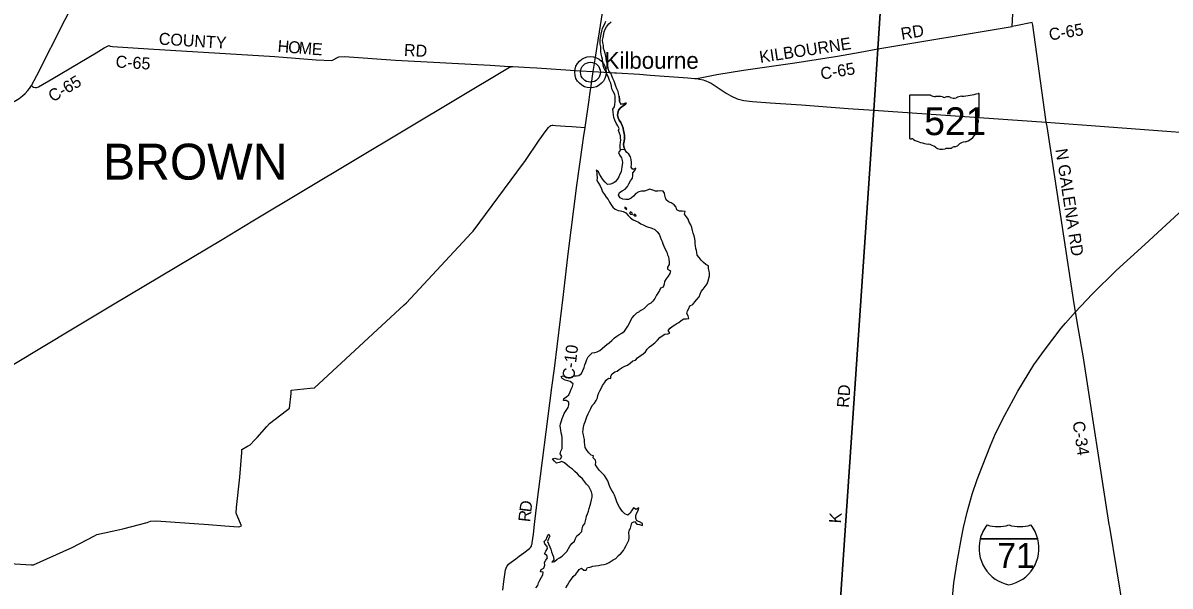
# Model space of a CAD drawing. Extents: x 1674899 to 2057726, y 653888 to 988278.
# Drawn here: x 1826739 to 1855438, y 836141 to 850231 of the extents above; entities that cross this region are included whole.
import ezdxf

# ---------------------------------------------------------------- set-up
doc = ezdxf.new("R2010")
doc.units = 0
for name, color, linetype in [('GM_X_County_Road', 7, 'Continuous'), ('GM_X_County_Road_Text', 7, 'Continuous'), ('GM_X_Interstate_Location', 7, 'Continuous'), ('GM_X_Interstate_Route', 7, 'Continuous'), ('GM_X_Interstate_Shield', 7, 'Continuous'), ('GM_X_Major_Lake', 7, 'Continuous'), ('GM_X_Major_River', 7, 'Continuous'), ('GM_X_State_Location', 7, 'Continuous'), ('GM_X_State_Route', 7, 'Continuous'), ('GM_X_State_Shield', 7, 'Continuous'), ('GM_X_Township', 7, 'Continuous'), ('GM_X_Township_Text', 7, 'Continuous'), ('GM_X_Unincorporated', 7, 'Continuous'), ('GM_X_Unincorporated_Location', 7, 'Continuous'), ('GM_X_Unincorporated_Text', 7, 'Continuous'), ('GM_X_US_Route', 7, 'Continuous'), ('SH_Data', 7, 'Continuous')]:
    doc.layers.add(name, color=color, linetype=linetype)

msp = doc.modelspace()

# ---------------------------------------------------------------- linework, layer by layer
at = {"layer": 'GM_X_County_Road'}
for points in [[(1841006, 849018), (1841051, 849314), (1841101, 849645), (1841295, 850857)], [(1852342, 847746), (1852332, 847819), (1852002, 850172), (1851992, 850242), (1851578, 850159), (1851485, 850140), (1851503, 850457)], [(1848128, 849585), (1851485, 850140)], [(1827483, 848845), (1828569, 849486), (1828773, 849606), (1828890, 849668)], [(1828890, 849668), (1828890, 849668), (1828924, 849648), (1828977, 849643), (1829879, 849585), (1833037, 849389), (1834076, 849311), (1834469, 849288), (1834642, 849380), (1834781, 849392), (1836063, 849299), (1838431, 849174), (1838783, 849153), (1838998, 849141)], [(1843595, 848838), (1843637, 848852), (1843852, 848894), (1844102, 848937), (1844768, 849049), (1846050, 849232), (1847118, 849400), (1847685, 849497), (1848128, 849585)], [(1846971, 832575), (1846971, 832575), (1847065, 833986), (1848030, 848046), (1848128, 849585)], [(1838743, 836040), (1838773, 836253), (1838796, 836429), (1838814, 836551), (1838826, 836590), (1838844, 836629), (1838867, 836664), (1838885, 836685), (1838954, 836740), (1839072, 836824), (1839157, 836890), (1839273, 836974), (1839413, 837081), (1839426, 837095), (1839438, 837110), (1839458, 837143), (1839466, 837161), (1839472, 837179), (1839477, 837198), (1839478, 837221), (1839510, 837440), (1839538, 837684), (1839547, 837760), (1839596, 838176), (1839967, 841111), (1840035, 841581), (1840259, 843439), (1840381, 844450), (1840596, 846166), (1840736, 847171), (1840762, 847354), (1840807, 847615), (1840906, 848311), (1840922, 848444), (1840955, 848656), (1841006, 849018)], [(1826954, 848664), (1826976, 848639), (1827002, 848628), (1827054, 848615), (1827084, 848617), (1827126, 848635), (1827483, 848845)], [(1824939, 836797), (1826941, 836673), (1827000, 836670), (1827915, 837079), (1827969, 837103), (1828528, 837401), (1828591, 837434), (1829159, 837555), (1829234, 837570), (1829847, 837731), (1829932, 837765), (1830068, 837770), (1831380, 837679), (1831789, 837651), (1832132, 837627), (1832164, 837633), (1832207, 837647), (1832086, 837925), (1832077, 837968), (1832081, 838107), (1832167, 838864), (1832211, 839479), (1832217, 839559), (1832354, 839640), (1832420, 839679), (1832530, 839793), (1832596, 839862), (1832843, 840137), (1832910, 840211), (1833329, 840531), (1833411, 840594), (1833446, 840962), (1833453, 841041), (1833926, 841092), (1834029, 841103), (1836280, 843180), (1836334, 843229), (1837952, 844970), (1838003, 845024), (1839263, 846719), (1839296, 846763), (1839657, 847296), (1839829, 847544), (1839890, 847618), (1839921, 847646), (1839949, 847661), (1839978, 847670), (1839994, 847672), (1840065, 847668), (1840312, 847648), (1840471, 847640), (1840580, 847631), (1840807, 847615)], [(1854821, 832136), (1854806, 832276), (1853927, 837618), (1853916, 837681), (1853270, 841855), (1853135, 842607), (1853071, 843001), (1853019, 843312), (1852359, 847640), (1852342, 847746)]]:
    msp.add_lwpolyline(points, dxfattribs=at)
at = {"layer": 'GM_X_Interstate_Route'}
for points in [[(1853497, 843457), (1854091, 844035), (1854810, 844689), (1856408, 846161), (1857196, 846884), (1857351, 847028)], [(1852825, 842723), (1853071, 843001), (1853486, 843445), (1853497, 843457)], [(1849960, 835440), (1849991, 835852), (1850027, 836225), (1850112, 836751), (1850219, 837345), (1850270, 837606), (1850358, 837993), (1850490, 838443), (1850609, 838810), (1850743, 839153), (1850946, 839662), (1851071, 839958), (1851303, 840416), (1851627, 841020), (1852032, 841680), (1852294, 842043), (1852715, 842598), (1852825, 842723)]]:
    msp.add_lwpolyline(points, dxfattribs=at)
at = {"layer": 'GM_X_Interstate_Shield'}
for p, q in [((1850686, 837319), (1852129, 837319)), ((1852129, 837319), (1850686, 837319)), ((1852129, 837319), (1850686, 837319))]:
    msp.add_line(p, q, dxfattribs=at)
for centre, start, end in [((1851595, 837089), 141.669, 165.8066), ((1851133, 838567), 253.0091, 286.9909), ((1851681, 838567), 253.0091, 286.9909), ((1851220, 837089), 14.1934, 38.331), ((1851595, 837089), 165.8066, 258.463), ((1851220, 837089), 281.537, 14.1934)]:
    msp.add_arc(centre, 938, start, end, dxfattribs=at)
at = {"layer": 'GM_X_Major_Lake'}
msp.add_line((1841794, 847067), (1841688, 847052), dxfattribs=at)
for points in [[(1841688, 847052), (1841636, 846990), (1841670, 846918), (1841715, 846857), (1841731, 846793), (1841737, 846743), (1841731, 846679), (1841720, 846623), (1841712, 846573), (1841702, 846509), (1841674, 846449), (1841648, 846383), (1841607, 846315), (1841553, 846256), (1841503, 846220), (1841435, 846194), (1841361, 846192), (1841301, 846244), (1841250, 846315), (1841202, 846381), (1841166, 846447), (1841135, 846507), (1841079, 846545), (1841096, 846477), (1841100, 846427), (1841102, 846359), (1841100, 846287), (1841140, 846223), (1841181, 846157), (1841217, 846081), (1841239, 846008), (1841290, 845940), (1841326, 845874), (1841380, 845812), (1841412, 845744), (1841451, 845677), (1841499, 845625), (1841559, 845571), (1841627, 845541), (1841687, 845529), (1841753, 845510), (1841818, 845478), (1841880, 845414), (1841942, 845353), (1842002, 845301), (1842067, 845277), (1842135, 845243), (1842201, 845204), (1842273, 845170), (1842339, 845140), (1842474, 845099), (1842544, 845061), (1842604, 845007), (1842652, 844945), (1842682, 844880), (1842707, 844816), (1842729, 844762), (1842751, 844704), (1842771, 844644), (1842808, 844574), (1842844, 844496), (1842868, 844429), (1842886, 844377), (1842897, 844311), (1842903, 844251), (1842907, 844185), (1842867, 844117), (1842865, 844067), (1842938, 844027), (1842924, 843959), (1842880, 843897), (1842830, 843827), (1842790, 843763), (1842777, 843697), (1842759, 843623), (1842693, 843597), (1842661, 843537), (1842623, 843473), (1842593, 843416), (1842548, 843340), (1842500, 843266), (1842446, 843220), (1842384, 843190), (1842330, 843136), (1842276, 843076), (1842212, 843047), (1842162, 843019), (1842162, 843013)], [(1843917, 843901), (1843913, 843907), (1843913, 843971), (1843904, 844021), (1843890, 844085), (1843892, 844154), (1843824, 844186), (1843766, 844238), (1843705, 844298), (1843655, 844359), (1843609, 844423), (1843599, 844489), (1843592, 844539), (1843576, 844589), (1843564, 844653), (1843558, 844707), (1843556, 844771), (1843551, 844831), (1843533, 844903), (1843509, 844972), (1843487, 845040), (1843476, 845114), (1843448, 845178), (1843406, 845248), (1843382, 845318), (1843339, 845381), (1843293, 845445), (1843303, 845513), (1843233, 845521), (1843165, 845523), (1843100, 845556), (1843080, 845622), (1843028, 845682), (1842960, 845726), (1842892, 845752), (1842829, 845803), (1842815, 845853), (1842799, 845921), (1842791, 845971), (1842757, 846025), (1842690, 846027), (1842626, 846024), (1842562, 846026), (1842498, 846048), (1842426, 846068), (1842356, 846047), (1842290, 846021), (1842216, 846019), (1842144, 846009), (1842076, 845963), (1842014, 845900), (1841952, 845850), (1841885, 845812), (1841818, 845812), (1841750, 845819), (1841682, 845851), (1841640, 845923), (1841666, 845989), (1841732, 846033), (1841802, 846071), (1841865, 846136), (1841893, 846208), (1841935, 846278), (1841989, 846348), (1841993, 846412), (1841998, 846480), (1842044, 846542), (1842074, 846594), (1842000, 846564), (1841958, 846620), (1841960, 846688), (1841961, 846739), (1841957, 846813), (1841939, 846881), (1841897, 846945), (1841836, 847001), (1841794, 847067)], [(1843917, 843901), (1843913, 843907), (1843913, 843971), (1843904, 844021), (1843890, 844085), (1843892, 844154), (1843824, 844186), (1843766, 844238), (1843705, 844298), (1843655, 844359), (1843609, 844423), (1843599, 844489), (1843592, 844539), (1843576, 844589), (1843564, 844653), (1843558, 844707), (1843556, 844771), (1843551, 844831), (1843533, 844903), (1843509, 844972), (1843487, 845040), (1843476, 845114), (1843448, 845178), (1843406, 845248), (1843382, 845318), (1843339, 845381), (1843293, 845445), (1843303, 845513), (1843233, 845521), (1843165, 845523), (1843100, 845556), (1843080, 845622), (1843028, 845682), (1842960, 845726), (1842892, 845752), (1842829, 845803), (1842815, 845853), (1842799, 845921), (1842791, 845971), (1842757, 846025), (1842690, 846027), (1842626, 846024), (1842562, 846026), (1842498, 846048), (1842426, 846068), (1842356, 846047), (1842290, 846021), (1842216, 846019), (1842144, 846009), (1842076, 845963), (1842014, 845900), (1841952, 845850), (1841885, 845812), (1841818, 845812), (1841750, 845819), (1841682, 845851), (1841640, 845923), (1841666, 845989), (1841732, 846033), (1841802, 846071), (1841865, 846136), (1841893, 846208), (1841935, 846278), (1841989, 846348), (1841993, 846412), (1841998, 846480), (1842044, 846542), (1842074, 846594), (1842000, 846564), (1841958, 846620), (1841960, 846688), (1841961, 846739), (1841957, 846813), (1841939, 846881), (1841897, 846945), (1841836, 847001), (1841794, 847067)], [(1841799, 845622), (1841793, 845596), (1841843, 845565)], [(1841843, 845565), (1841833, 845609), (1841799, 845622)], [(1841991, 845437), (1841982, 845472), (1841938, 845504), (1841910, 845472)], [(1841910, 845472), (1841941, 845448), (1841991, 845437)], [(1842071, 845423), (1842047, 845447), (1842013, 845431)], [(1842013, 845431), (1842041, 845403), (1842081, 845395), (1842071, 845423)], [(1843547, 843252), (1843601, 843310), (1843656, 843380), (1843682, 843446), (1843710, 843508), (1843756, 843572), (1843810, 843635), (1843855, 843707), (1843881, 843777), (1843917, 843901)], [(1842011, 838095), (1841961, 838027), (1841927, 837961), (1841869, 837914), (1841801, 837948), (1841741, 838004), (1841699, 838068), (1841661, 838119), (1841618, 838187), (1841598, 838251), (1841584, 838301), (1841566, 838351), (1841541, 838417), (1841505, 838483), (1841463, 838546), (1841431, 838606), (1841403, 838674), (1841372, 838774), (1841334, 838842), (1841288, 838907), (1841227, 838965), (1841167, 839031), (1841113, 839103), (1841067, 839174), (1841072, 839238), (1841060, 839292), (1841008, 839346), (1841012, 839398), (1840952, 839420), (1840897, 839478), (1840843, 839545), (1840805, 839611), (1840797, 839677), (1840786, 839741), (1840784, 839805), (1840772, 839873), (1840762, 839923), (1840750, 839989), (1840755, 840059), (1840765, 840121), (1840783, 840193), (1840803, 840247), (1840830, 840325), (1840850, 840377), (1840876, 840447), (1840946, 840587), (1840981, 840659), (1841039, 840719), (1841081, 840787), (1841109, 840853), (1841125, 840907), (1841149, 840973), (1841172, 841027), (1841210, 841099), (1841242, 841163), (1841286, 841226), (1841326, 841294), (1841385, 841346), (1841450, 841336), (1841443, 841392), (1841479, 841454), (1841549, 841498), (1841603, 841522), (1841657, 841563), (1841727, 841607), (1841799, 841641), (1841861, 841667), (1841927, 841719), (1841994, 841780), (1842060, 841792), (1842112, 841854), (1842178, 841904), (1842246, 841942), (1842310, 842001), (1842352, 842067), (1842412, 842123), (1842474, 842167), (1842545, 842223), (1842613, 842293), (1842669, 842360), (1842727, 842406), (1842801, 842446), (1842871, 842456), (1842923, 842470), (1842885, 842532), (1842932, 842598), (1842984, 842638), (1843044, 842679), (1843096, 842709), (1843146, 842737), (1843210, 842783), (1843270, 842831), (1843336, 842830), (1843402, 842832), (1843384, 842900), (1843352, 842958), (1843363, 843024), (1843395, 843084), (1843427, 843150), (1843495, 843184), (1843547, 843252)], [(1840224, 839259), (1840156, 839235), (1840090, 839215), (1840039, 839267), (1839985, 839322), (1840049, 839341), (1840117, 839319), (1840189, 839321), (1840217, 839383), (1840181, 839449), (1840197, 839515), (1840227, 839581), (1840226, 839645), (1840230, 839725), (1840232, 839791), (1840230, 839861), (1840223, 839913), (1840207, 839977), (1840197, 840043), (1840189, 840093), (1840183, 840150), (1840184, 840204), (1840210, 840272), (1840232, 840333), (1840254, 840391), (1840282, 840463), (1840331, 840533), (1840377, 840611), (1840399, 840675), (1840393, 840743), (1840333, 840781), (1840266, 840780), (1840274, 840838), (1840334, 840876), (1840396, 840929), (1840428, 840999), (1840456, 841065), (1840489, 841131), (1840501, 841205), (1840433, 841256), (1840371, 841276), (1840303, 841290), (1840231, 841332), (1840206, 841382), (1840258, 841400), (1840333, 841360), (1840397, 841354), (1840451, 841368), (1840521, 841399), (1840585, 841405), (1840649, 841409), (1840711, 841463), (1840750, 841531), (1840778, 841607), (1840800, 841673), (1840820, 841737), (1840845, 841808), (1840877, 841874), (1840981, 841974), (1841043, 841986), (1841107, 842004), (1841169, 842034), (1841233, 842087), (1841295, 842147), (1841345, 842185), (1841406, 842229), (1841470, 842289), (1841542, 842356), (1841594, 842396), (1841646, 842428), (1841722, 842472), (1841786, 842518), (1841838, 842594), (1841873, 842648), (1841913, 842723), (1841943, 842791), (1841977, 842853), (1842029, 842913), (1842100, 842975), (1842162, 843013)], [(1839568, 836094), (1839620, 836158), (1839641, 836218), (1839667, 836290), (1839713, 836360), (1839743, 836422), (1839755, 836490), (1839688, 836500), (1839702, 836556), (1839768, 836588), (1839792, 836660), (1839786, 836728), (1839822, 836792), (1839863, 836844), (1839849, 836910), (1839787, 836946), (1839823, 837018), (1839859, 837084), (1839850, 837134), (1839792, 837196), (1839780, 837257), (1839828, 837310), (1839850, 837376), (1839897, 837440), (1839918, 837388), (1839886, 837322), (1839866, 837258), (1839890, 837196), (1839919, 837124), (1839943, 837062), (1839965, 836996), (1839991, 836932), (1840016, 836869), (1840020, 836797), (1839970, 836735), (1840036, 836753), (1840100, 836811), (1840166, 836847), (1840232, 836891), (1840289, 836944), (1840347, 837008), (1840425, 837138), (1840471, 837202), (1840535, 837266), (1840564, 837330), (1840594, 837396), (1840662, 837446), (1840724, 837507), (1840732, 837573), (1840749, 837639), (1840795, 837705), (1840815, 837771), (1840829, 837839), (1840837, 837889), (1840865, 837949), (1840888, 838019), (1840906, 838085), (1840932, 838163), (1840944, 838221), (1840965, 838295), (1840977, 838367), (1840979, 838435), (1840967, 838499), (1840931, 838564), (1840894, 838632), (1840842, 838694), (1840788, 838758), (1840739, 838824), (1840675, 838883), (1840609, 838949), (1840547, 839009), (1840484, 839068), (1840416, 839120), (1840352, 839170), (1840286, 839226), (1840224, 839259)], [(1840324, 836096), (1840362, 836166), (1840408, 836241), (1840452, 836307), (1840508, 836379), (1840569, 836439), (1840617, 836505), (1840655, 836557), (1840713, 836587), (1840773, 836536), (1840827, 836540), (1840863, 836606), (1840931, 836618), (1840999, 836638), (1841067, 836647), (1841137, 836657), (1841205, 836671), (1841269, 836681), (1841335, 836697), (1841401, 836730), (1841453, 836764), (1841503, 836796), (1841571, 836834), (1841639, 836902), (1841705, 836965), (1841762, 837031), (1841790, 837083), (1841828, 837155), (1841894, 837287), (1841903, 837351), (1841903, 837401), (1841901, 837463), (1841909, 837529), (1841935, 837589), (1841956, 837657), (1841974, 837727), (1842042, 837753), (1842098, 837687), (1842168, 837684), (1842235, 837658), (1842236, 837708), (1842168, 837750), (1842100, 837771), (1842074, 837841), (1842072, 837907), (1842099, 837975), (1842141, 838045), (1842147, 838099), (1842079, 838061), (1842011, 838095)]]:
    msp.add_lwpolyline(points, dxfattribs=at)
at = {"layer": 'GM_X_Major_River'}
msp.add_line((1841794, 847067), (1841688, 847052), dxfattribs=at)
for points in [[(1841521, 847865), (1841513, 847931), (1841505, 847999), (1841494, 848071), (1841538, 848135), (1841544, 848191), (1841552, 848259), (1841559, 848329), (1841559, 848393), (1841547, 848443), (1841507, 848514), (1841474, 848580), (1841462, 848650), (1841444, 848724), (1841412, 848794), (1841387, 848862), (1841331, 848991), (1841293, 849059), (1841268, 849109), (1841252, 849179), (1841244, 849245), (1841238, 849323), (1841219, 849387), (1841207, 849449), (1841197, 849513), (1841193, 849580), (1841194, 849636), (1841180, 849700), (1841176, 849752), (1841176, 849816), (1841194, 849898), (1841203, 849954), (1841223, 850022), (1841239, 850090), (1841267, 850154), (1841293, 850206), (1841320, 850272)], [(1841655, 848397), (1841639, 848463), (1841627, 848513), (1841597, 848581), (1841574, 848653), (1841550, 848726), (1841526, 848776), (1841496, 848844), (1841471, 848908), (1841447, 848978), (1841395, 849036), (1841383, 849100), (1841370, 849169), (1841358, 849221), (1841340, 849273), (1841326, 849351), (1841319, 849401), (1841305, 849465), (1841291, 849521), (1841267, 849593), (1841260, 849667), (1841250, 849733), (1841242, 849802), (1841258, 849870), (1841279, 850010), (1841307, 850076), (1841341, 850135), (1841399, 850211), (1841452, 850263)], [(1841655, 848397), (1841660, 848319), (1841664, 848265), (1841700, 848199), (1841768, 848204), (1841834, 848234), (1841807, 848190), (1841756, 848156), (1841686, 848107), (1841636, 848047), (1841625, 847977), (1841617, 847927), (1841627, 847861), (1841659, 847800), (1841696, 847736), (1841728, 847668), (1841756, 847602), (1841764, 847534), (1841779, 847470), (1841787, 847406), (1841789, 847334), (1841779, 847270), (1841764, 847196), (1841772, 847131), (1841794, 847067)], [(1841794, 847067), (1841772, 847131), (1841764, 847196), (1841779, 847270), (1841789, 847334), (1841787, 847406), (1841779, 847470), (1841764, 847534), (1841756, 847602), (1841728, 847668), (1841696, 847736), (1841659, 847800), (1841627, 847861), (1841617, 847927), (1841625, 847977), (1841636, 848047), (1841686, 848107), (1841756, 848156), (1841807, 848190), (1841834, 848234), (1841768, 848204), (1841700, 848199), (1841664, 848265), (1841660, 848319), (1841655, 848397)], [(1841688, 847052), (1841682, 847118), (1841678, 847178), (1841689, 847246), (1841695, 847296), (1841691, 847358), (1841685, 847408), (1841665, 847470), (1841640, 847536), (1841654, 847588), (1841624, 847658), (1841582, 847725), (1841545, 847795), (1841521, 847865)]]:
    msp.add_lwpolyline(points, dxfattribs=at)
at = {"layer": 'GM_X_State_Route'}
for points in [[(1824240, 840319), (1825270, 840939), (1826096, 841440), (1826142, 841474), (1826514, 841694), (1827976, 842576), (1829017, 843200), (1831719, 844816), (1832490, 845282), (1838868, 849097), (1838914, 849121), (1838998, 849141), (1839418, 849116)], [(1839418, 849116), (1839597, 849106), (1840678, 849037), (1841006, 849018)], [(1841006, 849018), (1841537, 848985), (1841586, 848982)], [(1841586, 848982), (1842167, 848948), (1842431, 848928)], [(1842431, 848928), (1843370, 848858), (1843543, 848843)], [(1843543, 848843), (1843595, 848838), (1843668, 848826), (1843754, 848804), (1843796, 848791), (1843824, 848782), (1843899, 848751), (1843959, 848721), (1844210, 848561), (1844336, 848473), (1844448, 848406), (1844608, 848336), (1844771, 848292), (1844988, 848267), (1845431, 848234), (1846221, 848181), (1847382, 848093), (1848030, 848046), (1852342, 847746), (1853462, 847664), (1857695, 847346)]]:
    msp.add_lwpolyline(points, dxfattribs=at)
at = {"layer": 'GM_X_State_Shield'}
for p, q in [((1848919, 848406), (1848919, 847350)), ((1849446, 848425), (1848936, 848425)), ((1850659, 847898), (1850659, 848451)), ((1850659, 847898), (1850659, 847898))]:
    msp.add_line(p, q, dxfattribs=at)
for centre, major_axis, start_param, end_param in [((1848939, 848409), (20.2, 0), 1.712693, 3.28349), ((1849567, 848547), (196, 0), 4.042523, 4.731795), ((1849632, 847831), (702, 0), 1.404758, 1.657858), ((1849791, 848414), (56.4, 0), 3.836095, 5.185415), ((1849874, 848292), (117, 0), 0.950623, 2.079405), ((1850025, 848460), (141, 0), 4.081561, 5.145723), ((1850274, 848102), (371, 0), 1.699011, 2.107814), ((1850039, 849865), (1845, 0), 4.814394, 5.042369), ((1850640, 848453), (19.4, 0), 6.141152, 7.989035), ((1850654, 847858), (30, 0), 1.883978, 3.671073), ((1850464, 847788), (180, 0), 5.934695, 6.695948), ((1850638, 847896), (20.7, 0), 5.05454, 6.418171), ((1850142, 847596), (462, 0), 5.101752, 6.440018), ((1850728, 847667), (131, 0), 2.387724, 3.262537), ((1848939, 847348), (20.3, 0), 3.00124, 4.508301), ((1848942, 847456), (155, 0), 4.665946, 4.897461), ((1848974, 847289), (56, 0), 0.519207, 1.627899), ((1849680, 848238), (1333, 0), 4.195997, 4.488961), ((1850337, 847053), (253, 0), 1.647645, 2.488434), ((1849283, 846875), (417, 0), 0.823519, 1.323587), ((1849734, 847284), (265, 0), 4.026481, 4.996735), ((1849887, 846918), (217, 0), 1.495662, 1.94098), ((1849906, 847205), (141, 0), 4.691044, 5.507374), ((1850034, 847102), (39.7, 0), 1.147584, 2.315152), ((1850017, 847247), (149, 0), 4.937069, 5.64225)]:
    msp.add_ellipse(centre, major_axis=major_axis, ratio=0.8, start_param=start_param, end_param=end_param, dxfattribs=at)
at = {"layer": 'GM_X_Township'}
for points in [[(1820274, 835623), (1820357, 837080), (1820411, 838018), (1820789, 844650), (1820950, 847472), (1821204, 851968), (1821306, 853784), (1821743, 860915), (1823464, 860801), (1824857, 860710), (1830057, 860416), (1830089, 860410), (1830166, 860402), (1832694, 860243), (1832799, 860239), (1833125, 860220), (1836785, 859928), (1837275, 859897), (1843111, 859493), (1848243, 859177), (1848752, 859146), (1848128, 849585), (1848030, 848046), (1847065, 833986)], [(1858606, 831851), (1854821, 832136), (1851310, 832334), (1849737, 832422), (1846971, 832575), (1847065, 833986), (1848030, 848046), (1848128, 849585), (1848752, 859146), (1850615, 859080), (1861827, 858324)]]:
    msp.add_lwpolyline(points, dxfattribs=at)
at = {"layer": 'GM_X_Unincorporated'}
for radius in [393, 249]:
    msp.add_circle((1840937, 848998), radius, dxfattribs=at)
at = {"layer": 'GM_X_Unincorporated_Location'}
msp.add_line((1840937, 848998), (1840937, 848998), dxfattribs=at)
at = {"layer": 'GM_X_US_Route'}
msp.add_lwpolyline([(1826523, 848267), (1826643, 848340), (1826727, 848406), (1826792, 848465), (1826862, 848537), (1826902, 848592), (1826954, 848664), (1827089, 848914), (1827795, 850319), (1828063, 850849), (1828568, 851857), (1828794, 852323)], dxfattribs=at)
at = {"layer": 'SH_Data'}
for points in [[(1826523, 848267), (1826643, 848340), (1826727, 848406), (1826792, 848465), (1826862, 848537), (1826902, 848592), (1826954, 848664), (1827089, 848914), (1827795, 850319), (1828063, 850849), (1828568, 851857), (1828794, 852323)], [(1853497, 843457), (1854091, 844035), (1854810, 844689), (1856408, 846161), (1857196, 846884), (1857351, 847028)], [(1852825, 842723), (1853071, 843001), (1853486, 843445), (1853497, 843457)], [(1849960, 835440), (1849991, 835852), (1850027, 836225), (1850112, 836751), (1850219, 837345), (1850270, 837606), (1850358, 837993), (1850490, 838443), (1850609, 838810), (1850743, 839153), (1850946, 839662), (1851071, 839958), (1851303, 840416), (1851627, 841020), (1852032, 841680), (1852294, 842043), (1852715, 842598), (1852825, 842723)]]:
    msp.add_lwpolyline(points, dxfattribs=at)

# ---------------------------------------------------------------- texts
at = {"layer": 'GM_X_County_Road_Text'}
for s, rotation, p in [('RD', 9.4629, (1848728, 849808)), ('C-65', 9.349, (1852431, 849789)), ('COUNTY', 356.3619, (1830130, 849691)), ('H', 355.4088, (1833102, 849506)), ('KILBOURNE', 8.7281, (1845186, 849228)), ('O', 355.4052, (1833365, 849485)), ('M', 355.4334, (1833628, 849464)), ('E', 356.2566, (1833957, 849437)), ('RD', 357.0388, (1836266, 849409)), ('C-65', 356.2322, (1829050, 849119)), ('C-65', 9.2415, (1846716, 848811)), ('C-65', 30.5531, (1827483, 848240)), ('N GALENA RD', 278.7383, (1852569, 847065)), ('C-10', 83.1312, (1840527, 841296)), ('RD', 86.0533, (1847402, 840596)), ('C-34', 278.6148, (1852997, 840246)), ('R', 83.4128, (1839426, 837733)), ('D', 82.9224, (1839454, 837977)), ('K', 86.1842, (1847204, 837705))]:
    msp.add_text(s, height=300, rotation=rotation, dxfattribs=at).set_placement(p)
at = {"layer": 'GM_X_Interstate_Location'}
msp.add_text('71', height=1, rotation=0, dxfattribs=at).set_placement((1850037, 837232))
for s in ['.', '-', ',']:
    msp.add_text(s, height=1, dxfattribs=at).set_placement((1850241, 837439))
at = {"layer": 'GM_X_Interstate_Shield'}
msp.add_text('71', height=625, dxfattribs=at).set_placement((1851119, 836593))
at = {"layer": 'GM_X_State_Location'}
for s in ['s', 'r']:
    msp.add_text(s, height=1, dxfattribs=at).set_placement((1849769, 847808))
msp.add_text('521', height=1, rotation=0, dxfattribs=at).set_placement((1849416, 847735))
at = {"layer": 'GM_X_State_Shield'}
msp.add_text('521', height=696.1, dxfattribs=at).set_placement((1849287, 847424))
at = {"layer": 'GM_X_Township_Text'}
msp.add_text('BROWN', height=900, rotation=0, dxfattribs=at).set_placement((1828743, 846310))
at = {"layer": 'GM_X_Unincorporated_Text'}
msp.add_text('Kilbourne', height=417, rotation=0, dxfattribs=at).set_placement((1841290, 849084))

doc.saveas('drawing.dxf')
